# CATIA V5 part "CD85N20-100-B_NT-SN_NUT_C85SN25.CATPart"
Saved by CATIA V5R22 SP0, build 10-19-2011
Part number: CD85N20-100-B_NT-SN_NUT_C85SN25
Revision: ANY
Definition: UNKNOWN
Nomenclature: CD85N20-100-B_NT-SN_NUT_C85SN25
Source: Unknown
Bounding box of the stored display mesh (mm): x -16 to 16, y -18.475 to 18.475, z -5.5 to 5.5
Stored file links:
  D:\PER\CAO_PER_MODIF_2025\CAO_PER_pick&place_2024P\Sous_Ensemble_Flacon\CD85N20-100-B_NT-SN_NUT_C85SN25.CATPart
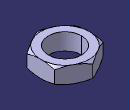
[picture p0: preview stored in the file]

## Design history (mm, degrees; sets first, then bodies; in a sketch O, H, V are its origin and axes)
Body1 "REVOLVE" (main body)
  Solid1: solid without history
